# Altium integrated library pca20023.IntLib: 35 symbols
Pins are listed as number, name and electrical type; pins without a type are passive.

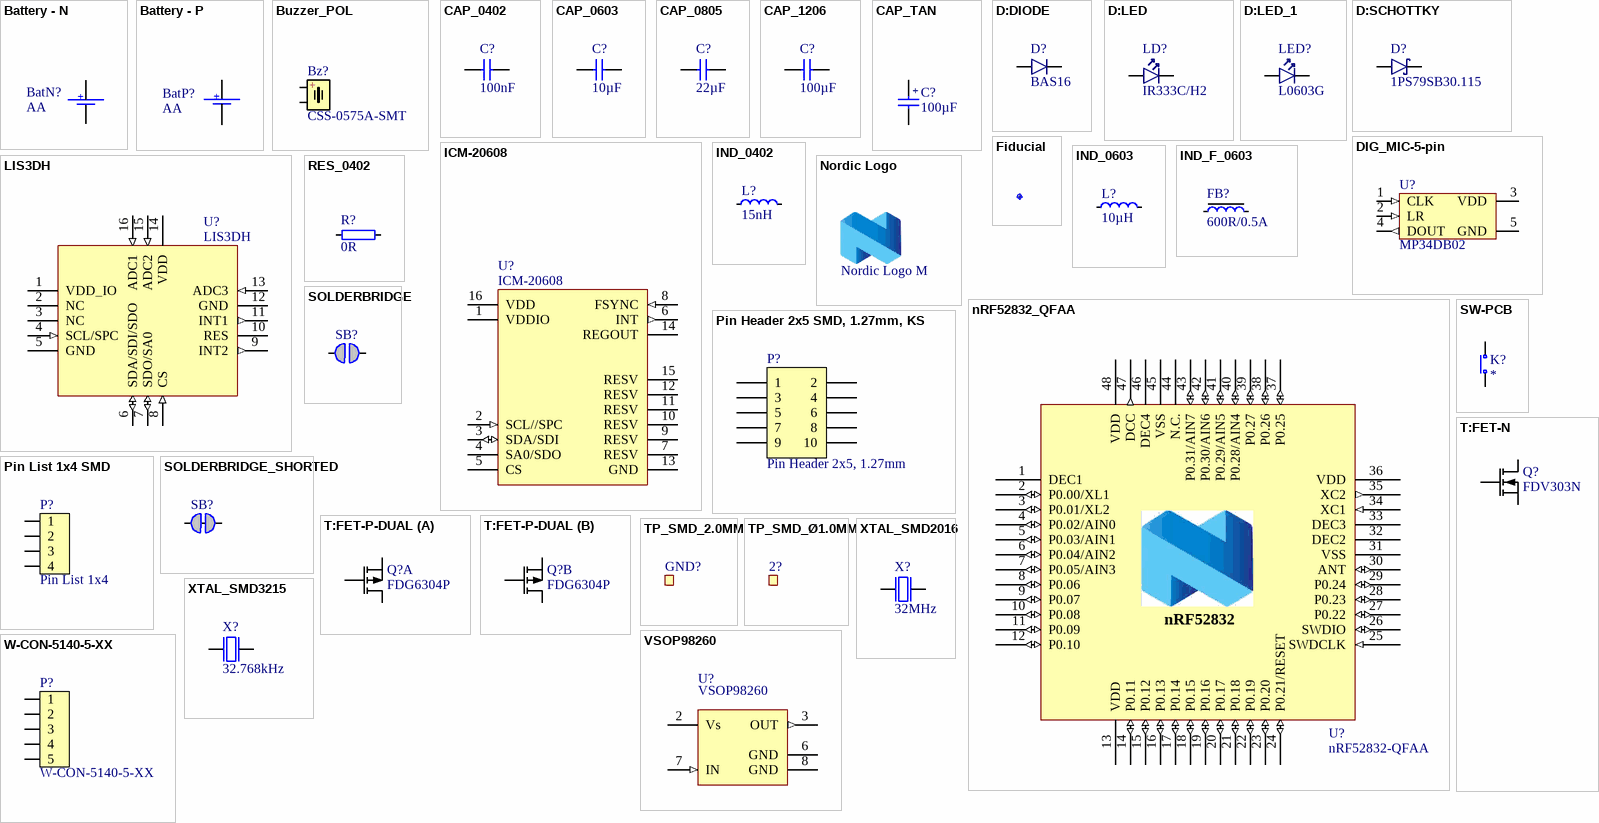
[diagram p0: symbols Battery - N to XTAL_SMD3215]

## Battery - N
designator BatN?, comment AA
Polsat Battery holder, Negative pole; Part Number: POLSATBATTERYHOLDER_N; Manufacturer Part Number: NA; Artikkelnr Noca: N.A.
footprint POLSATBATTERYHOLDER
pins: 1

## Battery - P
designator BatP?, comment AA
Polsat Battery holder, Positive pole; Part Number: POLSATBATTERYHOLDER_P; Manufacturer Part Number: NA; Artikkelnr Noca: N.A.
footprint POLSATBATTERYHOLDER
pins: 1

## Buzzer_POL
designator Bz?, comment CSS-0575A-SMT
Magnetic Buzzer, SMD, 5.0mm x 5.0mm x 1.9mm, 4.0kHz, 75dB @ 3V, 2-4Vp-p, 110mA; Manufacturer: CUI Inc.; 2nd source part number: 490-CSS-0575A-SMT-TR; Artikkelnr Noca: N.A.
footprint Buzzer_SMD_5x5_3-pin
pins: 1, 2

## CAP_0402
designator C?, comment 100nF
Capacitor, X7R, ±10%; Part Number: C0402-100n; Note: 16V; Artikkelnr Noca: 20039200; Artikkelnr Simpro: N.A.
footprint CAPC1005X04L
pins: 1, 2

## CAP_0603
designator C?, comment 10µF
Capacitor, X5R, ±20%; Part Number: C0603-10µ; Note: 6.3V; Artikkelnr Noca: 20039234; Artikkelnr Simpro: N.A.
footprint CAPC1608X06L
pins: 1, 2

## CAP_0805
designator C?, comment 22µF
Capacitor, X5R, ±10%; Part Number: C0805-22µ; Note: 6.3V; Artikkelnr Noca: 20039330; Artikkelnr Simpro: N.A.
footprint CAPC2012X11L
pins: 1, 2

## CAP_1206
designator C?, comment 100µF
CAP CER 100UF 6.3V 20% X5R 1206; Part Number: C1206-100u-6.3V; Manufacturer: Murata Electronics North America; Manufacturer Part Number: GRM31CR60J107ME39L; Artikkelnr Noca: N.A.
footprint CAPC3216X13L
pins: 1, 2

## CAP_TAN
designator C?, comment 100µF
Capacitor, Tantalum, ±10%; Part Number: C3528-100µF; Manufacturer: Vishay Sprague; Manufacturer Part Number: TR3B107K6R3C0500; Note: 6.3V; Artikkelnr Noca: N.A.
footprint CAPMP3528X21N
pins: 1, 2

## D:DIODE
designator D?, comment BAS16
Bas16 Diode; Artikkelnr Noca: 10019007; Artikkelnr Simpro: N.A.
footprint SOT-23a
pins: 1 A, 3 C

## D:LED
designator LD?, comment IR333C/H2
IR EMITTER, 3MM, 940NM; Part Number: IR333C/H2_SIDE; Manufacturer: Everlight; Artikkelnr Noca: N.A.
footprint LED_3MM_SIDE
pins: 1 C, 2 A

## D:LED_1
designator LED?, comment L0603G
LED 0603, EL19-21SYGC; Manufacturer: Everlight; Manufacturer Part Number: 19-21SYGC/S530-E1/TR8; Note: 16 mcd @ 20 mA; Artikkelnr Noca: 13019044; Artikkelnr Simpro: N.A.
footprint LED_0603_G
pins: 1 C, 2 A

## D:SCHOTTKY
designator D?, comment 1PS79SB30.115
Diode Schottky Vf=0.38, Vr=40V, If=200mA, Ir=500nA; Manufacturer: NXP; 2nd source part number: 873-4097; Artikkelnr Noca: 10029120; Artikkelnr Simpro: N.A.
footprint SOD-523
pins: 1 A, 3 C

## DIG_MIC-5-pin
designator U?, comment MP34DB02
MEMS audio sensor omnidirectional digital microphone; Manufacturer: STMicroelectronics; 2nd source part number: 511-MP34DB02TR; Note: Alternative: ADMP421, SPK0833LM4H-B, MP34DB01; Artikkelnr Noca: N.A.
footprint RHLGA-4 (3x4x1mm)
pins: 1 CLK (in), 2 LR (in), 3 VDD (power), 4 DOUT (out), 5 GND (power)

## Fiducial
designator Fid?, comment Fiducial mark  (value not drawn)
Part Number: Fid-Mark; Artikkelnr Noca: N.A.
footprint Fiducial

## ICM-20608
designator U?
Gyroscope and Accelerometer, PQFN-16; Manufacturer: InvenSense; Artikkelnr Noca: N.A.
footprint PQFN50P300X300X100-16N
pins: 1 VDDIO (power), 2 SCL//SPC (in), 3 SDA/SDI (io), 4 SA0/SDO, 5 CS, 6 INT (out), 7 RESV, 8 FSYNC (in), 9 RESV, 10 RESV, 11 RESV, 12 RESV, 13 GND (power), 14 REGOUT (power), 15 RESV, 16 VDD (power)

## IND_0402
designator L?, comment 15nH
Inductor, 320mA, ±5%; Part Number: L0402-15n; Manufacturer: Taiyo Yuden; Manufacturer Part Number: HK100515NJ-T; 2nd source part number: 658-1328; Note: High frequency chip inductor ±10%; Artikkelnr Noca: 33029323; Artikkelnr Simpro: N.A.
footprint INDC1005X04L
pins: 1, 2

## IND_0603
designator L?, comment 10µH
Inductor, 80mA, ±10%; Part Number: L0603-10µ; Manufacturer: Taiyo Yuden; Manufacturer Part Number: LBMF1608T100K; 2nd source part number: 178-6105; Note: LBMF1608T100K 10µH 80mA 0603; Artikkelnr Noca: 33029314; Artikkelnr Simpro: N.A.
footprint INDC1608X06L
pins: 1, 2

## IND_F_0603
designator FB?, comment 600R/0.5A
Ferrite Bead, 600 Ohm @ 100MHz, 500mA, 380 mOhm Max; Part Number: FB0603-600R@100MHz-500mA; Manufacturer: Murata; Manufacturer Part Number: BLM18AG601SN1; 2nd source part number: 490-1014-1-ND; Note: Chip EMIFIL Inductor Type Chip Ferrite Bead; Artikkelnr Noca: 37019100; Artikkelnr Simpro: N.A.
footprint INDC1608X06L
pins: 1, 2

## LIS3DH
designator U?
3-axis - ±2g/±4g/±8g/±16g digital output nano accelerometer; Manufacturer: STMicroelectronics; 2nd source part number: 187-2923; Note: MEMS digital output motion sensor ultra low-power high performance 3-axes "nano" accelerometer; Artikkelnr Noca: 15079978; Artikkelnr Simpro: N.A.
footprint PQFN50P300X300X100-16N
pins: 1 VDD_IO (power), 2 NC, 3 NC, 4 SCL/SPC (in), 5 GND (power), 6 SDA/SDI/SDO (io), 7 SDO/SA0 (io), 8 CS (in), 9 INT2 (out), 10 RES, 11 INT1 (out), 12 GND (power), 13 ADC3 (in), 14 VDD (power), 15 ADC2 (in), 16 ADC1 (in)

## Nordic Logo
designator LOGO?, comment Nordic Logo M  (no BOM)
Nordic Logo, medium size; Artikkelnr Noca: N.A.
footprint NORDIC_LOGO_M

## nRF52832_QFAA
designator U?, comment nRF52832-QFAA
Multi-protocol Bluetooth Low Energy, ANT and 2.4GHz proprietary system-on-chip; Manufacturer: Nordic Semiconductor; Artikkelnr Noca: 15079306; Artikkelnr Simpro: N.A.
footprint QFN40P600X600X90-48N
pins: 1 DEC1 (power), 2 P0.00/XL1 (io), 3 P0.01/XL2 (io), 4 P0.02/AIN0 (io), 5 P0.03/AIN1 (io), 6 P0.04/AIN2 (io), 7 P0.05/AIN3 (io), 8 P0.06 (io), 9 P0.07 (io), 10 P0.08 (io), 11 P0.09 (io), 12 P0.10 (io), 13 VDD (power), 14 P0.11 (io), 15 P0.12 (io), 16 P0.13 (io), 17 P0.14 (io), 18 P0.15 (io), 19 P0.16 (io), 20 P0.17 (io), 21 P0.18 (io), 22 P0.19 (io), 23 P0.20 (io), 24 P0.21/RESET (io), 25 SWDCLK (in), 26 SWDIO (io), 27 P0.22 (io), 28 P0.23 (io), 29 P0.24 (io), 30 ANT (io), 31 VSS (power), 32 DEC2 (power), 33 DEC3 (power), 34 XC1 (in), 35 XC2 (out), 36 VDD (power), 37 P0.25 (io), 38 P0.26 (io), 39 P0.27 (io), 40 P0.28/AIN4 (io), 41 P0.29/AIN5 (io), 42 P0.30/AIN6 (io), 43 P0.31/AIN7 (io), 44 N.C. (power), 45 VSS (power), 46 DEC4 (power), 47 DCC (out), 48 VDD (power), 49 GND (power) hidden to GND

## Pin Header 2x5 SMD, 1.27mm, KS
designator P?, comment Pin Header 2x5, 1.27mm
Pin Header 2x5, 1.27mm (50mil), SMD, Keying Shroud; Part Number: Pin Header 2x5 SMD, 1.27mm, KS; Manufacturer: W-CON; Manufacturer Part Number: 3132-10MS0BK00R1; 2nd source part number: FTSH-105-01-F-DV-K; Artikkelnr Noca: 55010009; Artikkelnr Simpro: N.A.
footprint HDR_2x5-SMD-1.27mm-K
pins: 1, 2, 3, 4, 5, 6, 7, 8, 9, 10

## Pin List 1x4 SMD
designator P?, comment Pin List 1x4
Pin List 1x4, 2.54mm (100mil), SMD; Part Number: Pin List 1x4 SMD; 2nd source part number: 179-8983; Artikkelnr Noca: 55019234; Artikkelnr Simpro: N.A.
footprint LIST_1x4_SMD
pins: 1, 2, 3, 4

## RES_0402
designator R?, comment 0R
Resistor, ±5%, 0.063W; Part Number: R0402-0R; Note: Chip Res 5%; Artikkelnr Noca: 27049000; Artikkelnr Simpro: N.A.; Value Ohm: 0
footprint RESC1005X04L
pins: 1, 2

## SOLDERBRIDGE
designator SB?, comment Solderbridge  (value not drawn)  (no BOM)
Artikkelnr Noca: N.A.
footprint Solderbridge
pins: 1 0, 2 1

## SOLDERBRIDGE_SHORTED
designator SB?, comment Solderbridge  (value not drawn)  (net tie, no BOM)
Shorted Solderbridge; Part Number: Solderbridge Shorted; Artikkelnr Noca: N.A.
footprint Solderbridge_Shorted
pins: 1 0, 2 1

## SW-PCB
designator K?  (no BOM)
Keyboard matrix switch; Part Number: KEY_SWITCH_SR3; Value: PCB SW; Artikkelnr Noca: N.A.
footprint PCB Switch
pins: 1 N.O, 2 COM

## T:FET-N
designator Q?, comment FDV303N
Mosfet FDV303N; 2nd source part number: FDV303NCT-ND; Note: Schottky; Artikkelnr Noca: 35029048; Artikkelnr Simpro: N.A.
footprint SOT-23a
pins: 1 G, 2 S, 3 D

## T:FET-P-DUAL
designator Q?, comment FDG6304P
Fairchild, FDG6304P, Dual P-Channel Digital FET; Manufacturer Part Number: FDG6304N; 2nd source part number: FDG6304PCT-ND; Artikkelnr Noca: 35029088; Artikkelnr Simpro: N.A.
footprint SOT65P210X100-6N
part A pins: 1 S1, 2 G1, 6 D1
part B pins: 3 D2, 4 S2, 5 G2

## TP_SMD_2.0MM
designator GND?, comment 2.0mm,SMD  (value not drawn)  (no BOM)
2.0x2.0mm SMD testpad; Part Number: TP_SMD_2.0MM; Manufacturer: Nordic Semiconductor; Artikkelnr Noca: N.A.
footprint TP_SMD_2.0mmX2.0mm
pins: 1

## TP_SMD_Ø1.0MM
designator 2?, comment Ø1.0mm,SMD  (value not drawn)  (no BOM)
1.0mm circular SMD testpad; Part Number: TP_SMD_Ø1.0MM; Manufacturer: Nordic Semiconductor; Artikkelnr Noca: N.A.
footprint TP_SMD_Ø1.0mm
pins: 1

## VSOP98260
designator U?
IC SIGNAL CONDITIONING QFN; Manufacturer: Vishay; Artikkelnr Noca: N.A.
footprint QFN50P200X200X80-8N
pins: 2 Vs (power), 3 OUT (out), 6 GND (power), 7 IN (in), 8 GND (power)

## W-CON-5140-5-XX
designator P?
*; Manufacturer: W-CON; Manufacturer Part Number: 5140-05-SMUWBX02; Artikkelnr Noca: N.A.
footprint W-CON-5140-5-XX
pins: 1, 2, 3, 4, 5

## XTAL_SMD2016
designator X?, comment 32MHz
XTAL SMD 2016, 32MHz, Cl=8pF, Tol: ±10ppm, Stab: ±10ppm; Part Number: XTAL_SMD2016_32MHz_8pF_Epson; Manufacturer: Epson Toyocom; Manufacturer Part Number: Q22FA12800025; Note: XTAL SMD 32.000MHz; Artikkelnr Noca: 22019238; Artikkelnr Simpro: N.A.
footprint BT-XTAL_2016
pins: 1 inp, 2 GND hidden to GND, 3 out, 4 GND hidden to GND

## XTAL_SMD3215
designator X?, comment 32.768kHz
XTAL SMD 3215, 32.768kHz, 9pF, ±20ppm; Part Number: XTAL_FC-135 32.768k; Manufacturer: Epson Toyocom; Manufacturer Part Number: FC-135 32.768KHZ ±20PPM,9.0PF; 2nd source part number: 127-8037; Note: XTAL SMD 32.768kHz, 3215; Artikkelnr Noca: 22019091; Artikkelnr Simpro: N.A.
footprint XTAL_3215
pins: 1 inp, 2 out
